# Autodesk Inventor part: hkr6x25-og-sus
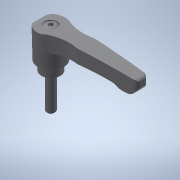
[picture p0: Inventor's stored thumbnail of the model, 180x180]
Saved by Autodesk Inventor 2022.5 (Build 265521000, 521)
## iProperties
Created: 2017-09
Part Number: hkr6x25-og-sus
Material: 一般
Document SubType Name: Modeling
Designer: imaocorp
Density: 1 g/cm^3
Appearance: 既定
Author: imaocorp
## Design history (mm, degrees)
node "hkr6x25-og-sus.x_t1"
node "hkr6x25-og-sus"
node "Base1"
